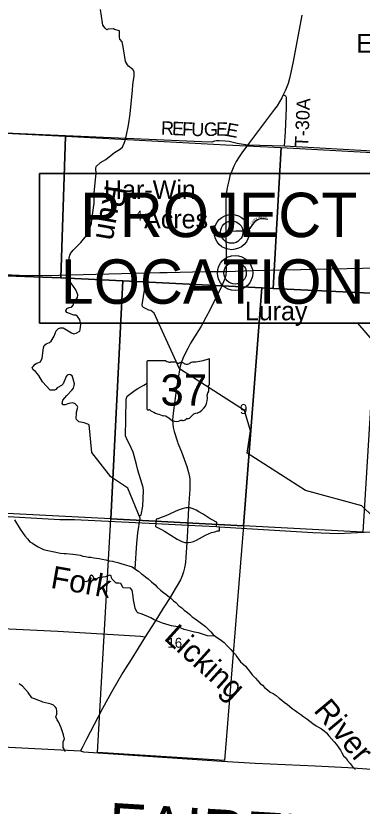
# Model space of a CAD drawing. Extents: x 0 to 40.4, y 0 to 22.
# Drawn here: x 3.509 to 4.97, y 14.615 to 17.952 of the extents above; entities that cross this region are included whole.
import ezdxf

# ---------------------------------------------------------------- set-up
doc = ezdxf.new("R2010")
doc.units = 0
for name, color, linetype in [('GM_X_Adjacent_County_Text', 7, 'Continuous'), ('GM_X_County', 7, 'Continuous'), ('GM_X_Interchange_Ramps', 7, 'Continuous'), ('GM_X_Interstate_Route', 7, 'Continuous'), ('GM_X_Major_River', 7, 'Continuous'), ('GM_X_Major_River_Text', 7, 'Continuous'), ('GM_X_Minor_River', 7, 'Continuous'), ('GM_X_Minor_River_Text', 7, 'Continuous'), ('GM_X_Section', 7, 'Continuous'), ('GM_X_Section_Text', 7, 'Continuous'), ('GM_X_State_Route', 7, 'Continuous'), ('GM_X_State_Shield', 7, 'Continuous'), ('GM_X_Township_Road', 7, 'Continuous'), ('GM_X_Township_Road_Text', 7, 'Continuous'), ('GM_X_Township_Subdivision', 7, 'Continuous'), ('GM_X_Township_Subdivision_Text', 7, 'Continuous'), ('GM_X_Unincorporated', 7, 'Continuous'), ('GM_X_Unincorporated_Text', 7, 'Continuous'), ('GM_X_US_Route', 7, 'Continuous'), ('SH_Masking', 7, 'Continuous'), ('SH_Text', 7, 'Continuous')]:
    doc.layers.add(name, color=color, linetype=linetype)

msp = doc.modelspace()

# ---------------------------------------------------------------- linework, layer by layer
at = {"layer": 'GM_X_County'}
msp.add_lwpolyline([(2.6, 14.9098), (3.7816, 14.849), (3.7947, 14.8444), (4.3781, 14.8049), (4.5187, 14.7962), (4.7718, 14.7855), (4.9113, 14.7777), (5.1259, 14.7632), (5.4221, 14.7453), (5.6303, 14.7317), (5.757, 14.7237), (5.765, 14.7235), (5.7951, 14.7228), (5.8513, 14.7168), (5.9456, 14.7103), (6.2034, 14.693), (6.2494, 14.69), (6.369, 14.682), (6.4224, 14.6785), (7.5441, 14.6124), (8.0846, 14.9692), (9.4, 14.8681)], dxfattribs=at)
at = {"layer": 'GM_X_Interchange_Ramps'}
for points in [[(4.2381, 15.8743), (4.2277, 15.8749), (4.2208, 15.8733), (4.2111, 15.8708), (4.1987, 15.8667), (4.1815, 15.8593), (4.1541, 15.8459), (4.1354, 15.8378), (4.1228, 15.8331), (4.1123, 15.8293), (4.1092, 15.8284), (4.107, 15.8278), (4.1007, 15.8263), (4.0998, 15.8089)], [(4.3559, 15.795), (4.3569, 15.8143), (4.3533, 15.8155), (4.3405, 15.8219), (4.3297, 15.8281), (4.2989, 15.8471), (4.2817, 15.8572), (4.2698, 15.864), (4.2569, 15.8702), (4.2442, 15.874), (4.2381, 15.8743)], [(4.0998, 15.8089), (4.0989, 15.796), (4.112, 15.7889), (4.1231, 15.7836), (4.1369, 15.776), (4.1892, 15.7428), (4.2091, 15.7329), (4.2227, 15.7279), (4.2311, 15.7276)], [(4.2311, 15.7276), (4.2365, 15.7275), (4.2473, 15.7294), (4.2584, 15.7327), (4.2712, 15.7384), (4.3098, 15.7585), (4.3352, 15.7699), (4.348, 15.7737), (4.3601, 15.7768), (4.3681, 15.7778), (4.3687, 15.7943)]]:
    msp.add_lwpolyline(points, dxfattribs=at)
at = {"layer": 'GM_X_Interstate_Route'}
for points in [[(4.2342, 15.8011), (4.3559, 15.795), (4.3687, 15.7943), (4.7616, 15.7706), (4.869, 15.7667), (5.0335, 15.7746), (5.2646, 15.7968), (5.5398, 15.8285), (5.6363, 15.8385), (6.0265, 15.8807), (6.202, 15.8998), (6.8841, 15.9717), (7.0777, 15.9919)], [(2.6, 15.8882), (3.6952, 15.8249), (3.7567, 15.8254), (4.0998, 15.8089), (4.2342, 15.8011)]]:
    msp.add_lwpolyline(points, dxfattribs=at)
at = {"layer": 'GM_X_Major_River'}
for points in [[(3.5041, 15.8233), (3.5124, 15.8104), (3.5192, 15.7983), (3.528, 15.7843), (3.5371, 15.7698), (3.5469, 15.7562), (3.5579, 15.7433), (3.5689, 15.7308), (3.5792, 15.7247), (3.589, 15.7182), (3.6034, 15.7103), (3.6148, 15.7049), (3.6258, 15.6992), (3.6376, 15.6958), (3.6505, 15.6924), (3.6633, 15.6897), (3.6728, 15.6882), (3.6842, 15.6863)], [(3.6842, 15.6863), (3.6975, 15.6833), (3.7127, 15.6821), (3.7221, 15.6818), (3.7358, 15.6802), (3.7491, 15.6791), (3.7604, 15.678), (3.7707, 15.6761), (3.7806, 15.6742), (3.7919, 15.6711), (3.8033, 15.6688), (3.8151, 15.6669), (3.8253, 15.6658), (3.8378, 15.6639), (3.8488, 15.6616), (3.8613, 15.6601), (3.8739, 15.6582), (3.8887, 15.6544), (3.9031, 15.651), (3.9163, 15.6491), (3.9273, 15.6468), (3.9399, 15.6441), (3.9524, 15.6396), (3.966, 15.635), (3.9755, 15.6327), (3.9865, 15.6297), (4.0002, 15.6251), (4.0157, 15.6145), (4.026, 15.6073), (4.0388, 15.5963), (4.0483, 15.5898), (4.0578, 15.5811), (4.0677, 15.5747), (4.0813, 15.5625), (4.0965, 15.55), (4.1056, 15.5401), (4.12, 15.5268), (4.1321, 15.517), (4.1416, 15.5098), (4.1511, 15.5029), (4.1617, 15.4942), (4.1742, 15.4817), (4.1837, 15.4745), (4.1974, 15.4612), (4.2088, 15.4517), (4.2198, 15.4418), (4.233, 15.4323), (4.2433, 15.4247), (4.2535, 15.4137), (4.2653, 15.4054), (4.2759, 15.3986), (4.2869, 15.391), (4.2975, 15.3815), (4.3096, 15.3739), (4.3203, 15.3629), (4.3316, 15.3511), (4.3396, 15.3416), (4.3502, 15.3329), (4.3597, 15.3257), (4.3715, 15.3181), (4.3878, 15.3056), (4.4007, 15.2923), (4.4155, 15.2771), (4.4249, 15.2672), (4.4352, 15.2559), (4.4409, 15.246), (4.45, 15.2342), (4.4564, 15.2247), (4.4667, 15.216), (4.4776, 15.2058), (4.4886, 15.194), (4.4955, 15.1845), (4.5065, 15.1693), (4.5205, 15.1549), (4.5296, 15.1447), (4.5402, 15.1329), (4.5497, 15.1253), (4.5603, 15.1151), (4.5709, 15.1056), (4.5827, 15.0965), (4.5941, 15.0911), (4.6077, 15.0828), (4.6206, 15.0714), (4.6309, 15.0627), (4.6419, 15.0543), (4.6548, 15.0441), (4.6642, 15.0372), (4.6745, 15.027), (4.687, 15.0194), (4.6988, 15.0103), (4.7113, 15.0023), (4.7242, 14.9925), (4.7371, 14.9837), (4.75, 14.9742), (4.7621, 14.9636), (4.7769, 14.9545), (4.7864, 14.9488), (4.7989, 14.9412), (4.8095, 14.9325), (4.8194, 14.9253), (4.8296, 14.9116)], [(4.8296, 14.9116), (4.8414, 14.8995), (4.852, 14.8866), (4.8622, 14.8756), (4.8717, 14.8619), (4.8793, 14.8509), (4.8842, 14.8399), (4.8922, 14.8281), (4.9024, 14.8175), (4.9081, 14.8076), (4.9195, 14.7951), (4.9275, 14.7841), (4.9388, 14.7727), (4.9406, 14.7701)]]:
    msp.add_lwpolyline(points, dxfattribs=at)
at = {"layer": 'GM_X_Minor_River'}
for points in [[(3.8392, 17.1732), (3.8396, 17.2043), (3.8471, 17.2733), (3.8483, 17.2866), (3.8464, 17.3075), (3.8484, 17.3158), (3.867, 17.3317), (3.8887, 17.3445), (3.9187, 17.3694), (3.9248, 17.3739), (3.9472, 17.3875), (3.9586, 17.3969), (3.969, 17.4208), (3.9751, 17.4428), (3.9851, 17.4905), (3.9918, 17.5379), (4.0016, 17.6376), (4.0032, 17.6604), (4.009, 17.6983), (4.0079, 17.7153), (4.003, 17.7245), (3.9845, 17.7386), (3.9803, 17.7447), (3.9713, 17.7583), (3.9624, 17.8206), (3.9575, 17.8422), (3.9484, 17.8525), (3.9466, 17.8608), (3.9459, 17.8889), (3.9258, 17.8935), (3.9205, 17.897), (3.8993, 17.8959), (3.8936, 17.8925), (3.886, 17.8997), (3.8766, 17.9127), (3.8743, 17.9214), (3.8666, 17.9787)], [(4.0108, 15.6178), (4.0122, 15.6189), (4.0201, 15.7247), (4.0244, 15.7695), (4.0334, 15.8309), (3.9822, 15.9578), (3.9103, 16.0051), (3.8298, 16.1074), (3.8181, 16.2243), (3.8128, 16.2277), (3.7976, 16.2331), (3.7745, 16.2369), (3.7654, 16.2476), (3.7636, 16.2533), (3.7648, 16.273), (3.7656, 16.2783), (3.7709, 16.2995), (3.7679, 16.3052), (3.7588, 16.3132), (3.749, 16.3171), (3.7334, 16.3156), (3.7179, 16.3088), (3.7088, 16.3096), (3.7042, 16.3153), (3.7069, 16.329), (3.7237, 16.349), (3.7461, 16.3706), (3.7522, 16.3797), (3.7557, 16.3914), (3.7561, 16.3982), (3.7497, 16.4237), (3.7467, 16.432), (3.7403, 16.4366), (3.7346, 16.437), (3.7259, 16.4344), (3.7213, 16.4291), (3.7087, 16.3976), (3.7014, 16.3908), (3.684, 16.381), (3.6779, 16.3746), (3.6726, 16.3716), (3.6661, 16.3712), (3.6543, 16.3713), (3.6215, 16.4063), (3.606, 16.4333), (3.592, 16.45), (3.5822, 16.4573), (3.5784, 16.4668), (3.5822, 16.4717), (3.5906, 16.4811), (3.5974, 16.4849), (3.6138, 16.4902), (3.6207, 16.5057), (3.6257, 16.5497), (3.6288, 16.5599), (3.6372, 16.5667), (3.6505, 16.5719), (3.6577, 16.578), (3.6707, 16.5999), (3.6787, 16.6223), (3.689, 16.6317), (3.6977, 16.6347), (3.7038, 16.6347), (3.7095, 16.6339), (3.7439, 16.6126), (3.7542, 16.6095), (3.764, 16.6117), (3.7785, 16.6204), (3.7811, 16.6253), (3.7831, 16.6504), (3.779, 16.6678), (3.7696, 16.6827), (3.7624, 16.6876), (3.754, 16.6884), (3.7241, 16.6995), (3.72, 16.7064), (3.7249, 16.7166), (3.7337, 16.7203), (3.7443, 16.7214), (3.7519, 16.7313), (3.7531, 16.7373), (3.7699, 16.7631), (3.771, 16.7733), (3.7616, 16.7953), (3.742, 16.8231), (3.7371, 16.8349), (3.7367, 16.8402), (3.7338, 16.8777), (3.7358, 16.8986), (3.7344, 16.9289), (3.7363, 16.9407), (3.7401, 16.9483), (3.7504, 16.9619), (3.7835, 16.9948), (3.8068, 17.0235), (3.8163, 17.0394), (3.8286, 17.075), (3.8294, 17.0913), (3.8375, 17.1414), (3.8395, 17.1611), (3.8392, 17.1732)], [(5.1551, 15.7028), (4.969, 15.8829), (4.7318, 15.9482), (4.485, 16.1047), (4.4989, 16.1998), (4.4738, 16.2849), (4.199, 16.4607), (4.0924, 16.6959), (4.0781, 16.7077), (4.0697, 16.7096), (4.0478, 16.7196), (4.044, 16.7238), (4.0417, 16.7314), (4.058, 16.8292)], [(4.0297, 15.84), (4.0376, 15.8445), (4.0445, 15.8817), (4.0478, 15.9477), (4.0459, 15.9602), (4.0234, 16.0331), (4.0178, 16.0574), (4.0047, 16.109), (3.9881, 16.1432), (3.9783, 16.1611), (3.9716, 16.1778), (3.9733, 16.2491), (3.9748, 16.3333), (3.9782, 16.3458), (4.0124, 16.3711), (4.0235, 16.3783), (4.0497, 16.3922), (4.0634, 16.4013)], [(4.3498, 15.3332), (4.3177, 15.3337), (4.2802, 15.3463), (4.2628, 15.3498), (4.2196, 15.3609), (4.1927, 15.3717), (4.1665, 15.3759), (4.1559, 15.3798), (4.1278, 15.3874), (4.0926, 15.4012), (4.0786, 15.4108), (4.0415, 15.4257), (4.024, 15.4307), (4.0191, 15.4349), (4.0127, 15.4516), (4.0056, 15.4865), (4.0027, 15.5119), (4.002, 15.5173), (3.9997, 15.5271), (3.9929, 15.5355), (3.9614, 15.5368), (3.9516, 15.555), (3.9433, 15.5569), (3.9323, 15.5562), (3.9157, 15.5733), (3.9134, 15.5794), (3.9108, 15.5874), (3.9055, 15.5897), (3.888, 15.5829), (3.8561, 15.5785), (3.8462, 15.5694), (3.8413, 15.5729), (3.8341, 15.5865), (3.8277, 15.5907), (3.8224, 15.5877), (3.8201, 15.5794), (3.8178, 15.5729), (3.8124, 15.5646), (3.8041, 15.5616), (3.7946, 15.5635)], [(3.7182, 14.8457), (3.7084, 14.8628), (3.7085, 14.8875), (3.7138, 14.8984), (3.7101, 14.9167), (3.7011, 14.9459), (3.689, 14.9714), (3.683, 14.9797), (3.6773, 14.9915), (3.6816, 15.0029), (3.6827, 15.0162), (3.6805, 15.0272), (3.6771, 15.0332), (3.668, 15.042), (3.6586, 15.0458), (3.6229, 15.0543), (3.6173, 15.0566), (3.5767, 15.0727), (3.5609, 15.0947), (3.5367, 15.121), (3.5238, 15.1313)]]:
    msp.add_lwpolyline(points, dxfattribs=at)
at = {"layer": 'GM_X_Section'}
for points in [[(2.8217, 17.4882), (3.7188, 17.4429), (3.6994, 16.8455), (3.4311, 16.856), (2.9088, 16.8816), (2.7891, 16.8878)], [(3.7188, 17.4429), (4.3954, 17.4076), (4.6284, 17.3961), (4.5943, 16.8006), (4.5463, 16.803), (3.9609, 16.8328), (3.6994, 16.8455)], [(4.6284, 17.3961), (5.6266, 17.3411), (6.4444, 17.2982), (6.4106, 16.9046), (6.3929, 16.7053), (6.0805, 16.728), (5.57, 16.7542), (5.0349, 16.7787), (4.5943, 16.8006)], [(3.6994, 16.8455), (3.9609, 16.8328), (3.9098, 15.8281), (3.3882, 15.8552), (3.4311, 16.856)], [(3.9609, 16.8328), (4.5463, 16.803), (4.4702, 15.7981), (3.9098, 15.8281)], [(4.5463, 16.803), (4.5943, 16.8006), (5.0349, 16.7787), (4.9725, 15.7713), (4.4702, 15.7981)], [(3.9098, 15.8281), (4.4702, 15.7981), (4.389, 14.8078), (3.853, 14.8411)]]:
    msp.add_lwpolyline(points, close=True, dxfattribs=at)
at = {"layer": 'GM_X_State_Route'}
for points in [[(4.7164, 17.9544), (4.6792, 17.7593), (4.67, 17.7117), (4.6643, 17.6874), (4.6582, 17.6662), (4.647, 17.6377), (4.6374, 17.618), (4.6317, 17.6053), (4.6219, 17.5884), (4.6112, 17.5723), (4.6008, 17.558), (4.5078, 17.4337), (4.4859, 17.4056), (4.4624, 17.3729), (4.4514, 17.357), (4.4391, 17.3363), (4.4293, 17.3169), (4.4202, 17.2951), (4.4126, 17.2754), (4.4072, 17.2552), (4.4029, 17.2374), (4.3993, 17.2183), (4.3966, 17.1938), (4.3952, 17.1697), (4.3947, 17.1463), (4.3952, 17.0416), (4.396, 16.9408), (4.3966, 16.8721)], [(4.3966, 16.8721), (4.3945, 16.858), (4.3919, 16.846), (4.3856, 16.8292), (4.3763, 16.8085), (4.3286, 16.7111), (4.311, 16.6774), (4.2891, 16.6385), (4.2631, 16.5969), (4.2467, 16.5693), (4.2345, 16.5472), (4.2214, 16.5209), (4.2142, 16.5053), (4.2082, 16.4895), (4.2028, 16.4729), (4.1874, 16.3817), (4.1727, 16.2737), (4.1705, 16.246), (4.1714, 16.2273), (4.1727, 16.2135), (4.1766, 16.1972), (4.191, 16.1538), (4.1932, 16.1481)], [(4.1932, 16.1481), (4.2078, 16.1104), (4.23, 16.0493), (4.2382, 16.0231), (4.2418, 16.0055), (4.2426, 15.9951)], [(4.2426, 15.9951), (4.2434, 15.9841), (4.2436, 15.9539), (4.2381, 15.8743), (4.235, 15.8157)], [(4.235, 15.8157), (4.2342, 15.8011), (4.2311, 15.7276), (4.2293, 15.7065), (4.227, 15.666), (4.225, 15.6442), (4.2212, 15.621), (4.217, 15.6049), (4.211, 15.5874), (4.2036, 15.5707), (4.1902, 15.5473), (4.1632, 15.5018), (4.1624, 15.5005)], [(4.1624, 15.5005), (4.1311, 15.4511), (4.0955, 15.3933), (4.0553, 15.3297), (3.9955, 15.2345), (3.961, 15.1792), (3.9133, 15.0965), (3.8747, 15.0268), (3.8549, 14.9891)], [(3.8549, 14.9891), (3.8074, 14.8984), (3.7883, 14.8618), (3.7816, 14.849)], [(3.7816, 14.849), (3.7947, 14.8444), (4.3781, 14.8049), (4.5187, 14.7962), (4.7718, 14.7855), (4.9113, 14.7777), (5.1259, 14.7632)]]:
    msp.add_lwpolyline(points, dxfattribs=at)
at = {"layer": 'GM_X_State_Shield'}
for p, q in [((4.0625, 16.492), (4.0625, 16.2919)), ((4.1423, 16.4955), (4.0651, 16.4955)), ((4.3261, 16.3957), (4.3261, 16.5004)), ((4.3261, 16.3958), (4.3261, 16.3957))]:
    msp.add_line(p, q, dxfattribs=at)
for centre, radius, start, end in [((4.0655, 16.4924), 0.00305, 98.1301, 188.1301), ((4.1607, 16.5187), 0.0296, 231.6195, 271.1119), ((4.1705, 16.3831), 0.1064, 80.4867, 94.9883), ((4.1946, 16.4935), 0.00855, 219.7921, 297.1024), ((4.2072, 16.4703), 0.0178, 54.4667, 119.1411), ((4.2301, 16.5021), 0.0214, 233.8562, 294.8282), ((4.2679, 16.4343), 0.0563, 97.3462, 120.7689), ((4.2322, 16.7683), 0.2796, 275.8445, 288.9065), ((4.3232, 16.5008), 0.00294, 351.8621, 97.738), ((4.3255, 16.388), 0.00454, 107.944, 210.337), ((4.2966, 16.3748), 0.0273, 340.033, 23.6496), ((4.323, 16.3953), 0.00314, 289.6038, 7.7341), ((4.3367, 16.3519), 0.0198, 136.8065, 186.9296), ((4.2479, 16.3386), 0.0699, 292.3089, 8.9858), ((4.0655, 16.2915), 0.00308, 171.9584, 258.3066), ((4.066, 16.3119), 0.0235, 267.339, 280.6039), ((4.0708, 16.2803), 0.00848, 29.7484, 93.2717), ((4.1779, 16.4601), 0.2019, 240.4129, 257.1985), ((4.1177, 16.202), 0.0632, 47.1842, 75.836), ((4.2314, 16.245), 0.00601, 65.7517, 132.6484), ((4.2288, 16.2725), 0.0226, 282.8732, 323.2771), ((4.2774, 16.2357), 0.0383, 94.4031, 142.5768), ((4.186, 16.2794), 0.0401, 230.7004, 286.2918), ((4.2092, 16.2102), 0.0329, 85.6951, 111.2099), ((4.2121, 16.2644), 0.0214, 268.777, 315.5493)]:
    msp.add_arc(centre, radius, start, end, dxfattribs=at)
at = {"layer": 'GM_X_Township_Road'}
for points in [[(4.643, 17.4008), (4.6469, 17.4629), (4.6506, 17.5635), (4.6516, 17.5986), (4.6511, 17.6073), (4.6478, 17.6127), (4.6374, 17.618)], [(4.4859, 17.4056), (4.4431, 17.4123), (4.4091, 17.4206), (4.3923, 17.4227), (4.3672, 17.4238), (4.3555, 17.4234), (4.3471, 17.4218), (4.336, 17.4187), (4.2943, 17.4194), (2.6, 17.494)], [(4.643, 17.4008), (4.643, 17.4008), (4.4859, 17.4056)], [(5.5313, 17.3504), (5.475, 17.3518), (5.1375, 17.3729), (4.643, 17.4008)], [(3.4516, 15.3644), (3.6869, 15.3532), (3.9195, 15.3399), (4.0355, 15.3333), (4.0553, 15.3297)]]:
    msp.add_lwpolyline(points, dxfattribs=at)
at = {"layer": 'GM_X_Township_Subdivision'}
msp.add_lwpolyline([(4.3952, 17.0416), (4.4375, 17.0432), (4.462, 17.0432), (4.4736, 17.044), (4.4815, 17.0461), (4.4885, 17.0498), (4.4939, 17.0522), (4.4992, 17.0572), (4.5061, 17.0663), (4.5127, 17.0766), (4.521, 17.0862), (4.5272, 17.0907), (4.5382, 17.0944), (4.5532, 17.0955), (4.5717, 17.0936)], dxfattribs=at)
at = {"layer": 'GM_X_Unincorporated'}
for centre, radius in [((4.42, 17.0387), 0.0744), ((4.42, 17.0387), 0.0472), ((4.4341, 16.866), 0.0744), ((4.4341, 16.866), 0.0472)]:
    msp.add_circle(centre, radius, dxfattribs=at)
at = {"layer": 'GM_X_US_Route'}
for points in [[(4.1165, 16.8674), (4.1481, 16.8682), (4.3083, 16.8723), (4.3966, 16.8721), (4.51, 16.8761), (4.6467, 16.8788), (5.1665, 16.8908), (5.235, 16.8921), (5.3466, 16.8949), (5.3786, 16.8959), (5.4095, 16.9005), (5.4363, 16.9064), (5.5092, 16.9213), (5.5103, 16.9215)], [(3.2062, 16.872), (3.2196, 16.8713), (3.4616, 16.859), (3.5232, 16.8565), (3.639, 16.856), (3.7926, 16.8594), (4.1165, 16.8674)]]:
    msp.add_lwpolyline(points, dxfattribs=at)
at = {"layer": 'SH_Masking'}
msp.add_lwpolyline([(3.6095, 17.2863), (5.1487, 17.2863), (5.1487, 16.6545), (3.6095, 16.6545)], close=True, dxfattribs=at)
at = {"layer": 'SH_Text'}
msp.add_lwpolyline([(5.1487, 17.2863), (3.6095, 17.2863), (3.6095, 16.6545), (5.1487, 16.6545)], dxfattribs=at)
msp.add_lwpolyline([(5.4618, 16.061), (4.9515, 16.6545), (5.1487, 16.6545)], close=True, dxfattribs=at)

# ---------------------------------------------------------------- texts
at = {"layer": 'GM_X_Adjacent_County_Text'}
msp.add_text('FAIRFIELD COUNTY', height=0.189394, rotation=356.4928, dxfattribs=at).set_placement((3.8944, 14.4406))
at = {"layer": 'GM_X_Major_River_Text'}
for s, height, rotation, p in [('Fork', 0.09469, 349.9976, (3.6524, 15.5372)), ('Licking', 0.0947, 317.9938, (4.1298, 15.3209)), ('River', 0.09471, 309.9946, (4.7619, 15.0179))]:
    msp.add_text(s, height=height, rotation=rotation, dxfattribs=at).set_placement(p)
at = {"layer": 'GM_X_Minor_River_Text'}
msp.add_text('Run', height=0.0947, rotation=260.0008, dxfattribs=at).set_placement((3.8862, 17.2414))
at = {"layer": 'GM_X_Section_Text'}
for s, height, p in [('4', 0.0419, (4.012, 17.0875)), ('9', 0.0419, (4.4545, 16.2705)), ('16', 0.04186, (4.1486, 15.2838))]:
    msp.add_text(s, height=height, rotation=0, dxfattribs=at).set_placement(p)
at = {"layer": 'GM_X_State_Shield'}
msp.add_text('37', height=0.13184, dxfattribs=at).set_placement((4.1194, 16.306))
at = {"layer": 'GM_X_Township_Road_Text'}
for s, height, rotation, p in [('T-30A', 0.05682, 87.4212, (4.7422, 17.3961)), ('R', 0.0568, 357.5405, (4.1206, 17.4503)), ('E', 0.0568, 357.535, (4.1672, 17.4483)), ('F', 0.0568, 357.538, (4.2097, 17.4464)), ('U', 0.0568, 357.5737, (4.248, 17.4448)), ('G', 0.0568, 3.5307, (4.3044, 17.4427)), ('E', 0.0568, 358.7185, (4.3531, 17.4458)), ('E', 0.0568, 349.2574, (4.3931, 17.4451))]:
    msp.add_text(s, height=height, rotation=rotation, dxfattribs=at).set_placement(p)
at = {"layer": 'GM_X_Township_Subdivision_Text'}
for s, rotation, p in [('A', 52.1902, (4.5098, 17.0749)), ('R', 49.0905, (4.5148, 17.0814)), ('O', 36.3279, (4.5193, 17.0867)), ('L', 23.0192, (4.5255, 17.0914)), ('I', 17.5365, (4.5314, 17.0939)), ('N', 10.3283, (4.5351, 17.0951)), ('E', 3.3889, (4.543, 17.0965)), ('D', 357.5949, (4.5519, 17.097)), ('R', 355.795, (4.5602, 17.0967)), ('C', 54.451, (4.5055, 17.0689))]:
    msp.add_text(s, height=0.00947, rotation=rotation, dxfattribs=at).set_placement(p)
at = {"layer": 'GM_X_Unincorporated_Text'}
for s, p in [('Estates', (4.9453, 17.7962)), ('Har-Win', (3.8811, 17.1787)), ('Acres', (4.0503, 17.0545)), ('Luray', (4.4753, 16.6662))]:
    msp.add_text(s, height=0.07898, rotation=0, dxfattribs=at).set_placement(p)
at = {"layer": 'SH_Text'}
for s, p in [('PROJECT', (3.7804, 17.0173)), ('LOCATION', (3.6985, 16.736))]:
    msp.add_text(s, height=0.1875, dxfattribs=at).set_placement(p)

doc.saveas('drawing.dxf')
